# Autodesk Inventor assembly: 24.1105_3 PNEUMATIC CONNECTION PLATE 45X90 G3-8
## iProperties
Created: 2007-06
Part Number: 24.1105_3 PNEUMATIC CONNECTION PLATE 45X90 G3-8
Document SubType Name: Assembly
Designer: Andy Moles
Author: Andy Moles
